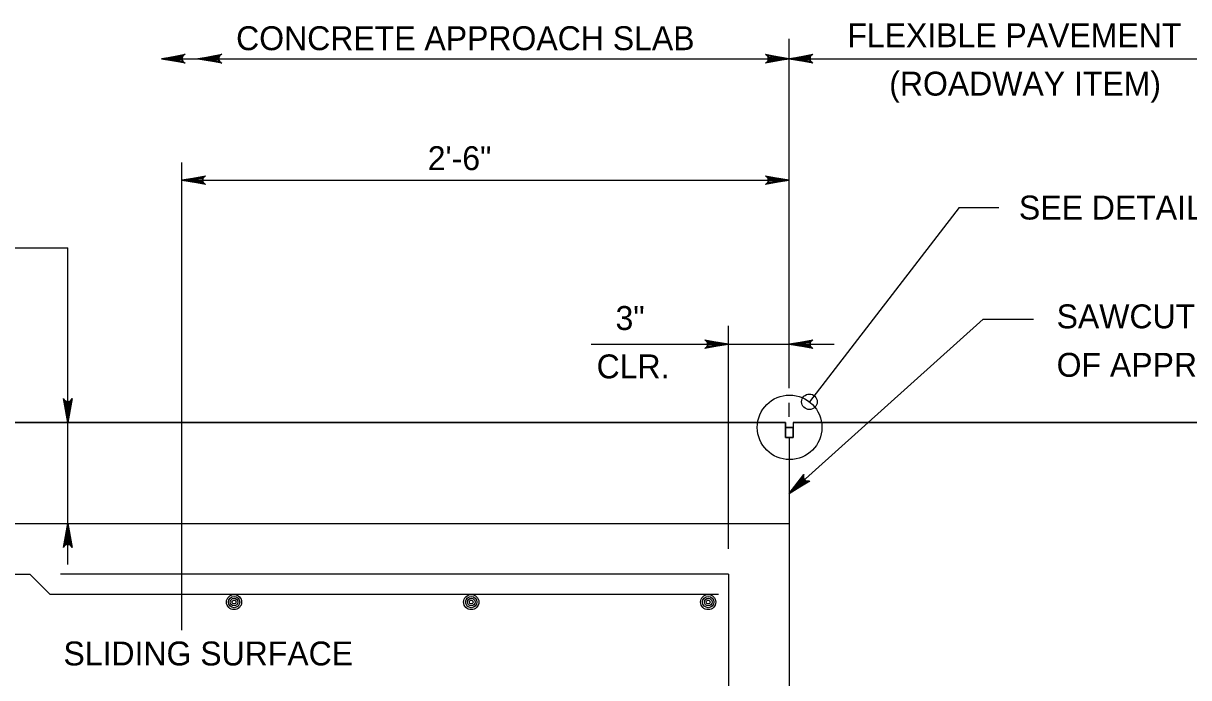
# Model space of a CAD drawing. Extents: x 636530 to 644067, y 294168 to 299122.
# Drawn here: x 639138.6 to 639284.8, y 297431.6 to 297513.7 of the extents above; entities that cross this region are included whole.
import ezdxf

# ---------------------------------------------------------------- set-up
doc = ezdxf.new("R2010")
doc.units = 0
doc.layers.add('1', color=7, linetype='Continuous')

msp = doc.modelspace()

# ---------------------------------------------------------------- linework, layer by layer
at = {"layer": '1'}
for p, q in [((639234.69, 297467.9), (639234.69, 297511.72)), ((639155.94, 297509.24), (639234.69, 297509.24)), ((639234.69, 297509.24), (639301.8, 297509.24)), ((639158.49, 297437.55), (639158.49, 297496.22)), ((639158.49, 297494), (639234.69, 297494)), ((639256.02, 297490.57), (639237.22, 297466.19)), ((639256.02, 297490.57), (639260.99, 297490.57)), ((639092.77, 297485.51), (639144.18, 297485.51)), ((639144.18, 297445.78), (639144.18, 297485.51)), ((639234.69, 297454.67), (639259.02, 297476.54)), ((639259.02, 297476.54), (639265.35, 297476.54)), ((639227.07, 297447.76), (639227.07, 297475.71)), ((639209.86, 297473.42), (639240.35, 297473.42)), ((639234.69, 297464.29), (639234.69, 297466.06)), ((639092.35, 297463.6), (639234.21, 297463.6)), ((639234.21, 297463.6), (639234.21, 297461.7)), ((639235.17, 297463.6), (639235.17, 297461.7)), ((639235.17, 297463.6), (639386.18, 297463.6)), ((639234.21, 297462.97), (639235.17, 297462.97)), ((639234.21, 297461.7), (639235.17, 297461.7)), ((639234.69, 297461.7), (639234.69, 297410.26)), ((639092.35, 297450.9), (639234.69, 297450.9)), ((639092.35, 297444.55), (639139.44, 297444.55)), ((639141.98, 297442.01), (639139.44, 297444.55)), ((639227.07, 297444.55), (639143.25, 297444.55)), ((639227.07, 297444.55), (639227.07, 297417.89)), ((639225.8, 297442.01), (639141.98, 297442.01))]:
    msp.add_line(p, q, dxfattribs=at)
for points in [[(639155.94, 297509.24), (639158.92, 297509.8), (639158.8, 297509.72), (639158.69, 297509.64), (639158.63, 297509.54), (639158.57, 297509.44), (639158.55, 297509.34), (639158.54, 297509.24), (639158.55, 297509.14), (639158.57, 297509.04), (639158.63, 297508.94), (639158.69, 297508.84), (639158.8, 297508.76), (639158.92, 297508.68), (639155.94, 297509.24), (639158.8, 297508.76), (639158.69, 297508.84), (639155.94, 297509.24), (639158.63, 297508.94), (639158.57, 297509.04), (639155.94, 297509.24), (639158.55, 297509.14), (639158.54, 297509.24), (639155.94, 297509.24), (639158.55, 297509.34), (639158.57, 297509.44), (639155.94, 297509.24), (639158.63, 297509.54), (639158.69, 297509.64), (639155.94, 297509.24), (639158.8, 297509.72)], [(639160.51, 297509.24), (639163.49, 297509.8), (639163.38, 297509.72), (639163.26, 297509.64), (639163.2, 297509.54), (639163.14, 297509.44), (639163.12, 297509.34), (639163.11, 297509.24), (639163.12, 297509.14), (639163.14, 297509.04), (639163.2, 297508.94), (639163.26, 297508.84), (639163.38, 297508.76), (639163.49, 297508.68), (639160.51, 297509.24), (639163.38, 297508.76), (639163.26, 297508.84), (639160.51, 297509.24), (639163.2, 297508.94), (639163.14, 297509.04), (639160.51, 297509.24), (639163.12, 297509.14), (639163.11, 297509.24), (639160.51, 297509.24), (639163.12, 297509.34), (639163.14, 297509.44), (639160.51, 297509.24), (639163.2, 297509.54), (639163.26, 297509.64), (639160.51, 297509.24), (639163.38, 297509.72)], [(639234.69, 297509.24), (639231.71, 297508.68), (639231.82, 297508.76), (639231.94, 297508.84), (639232, 297508.94), (639232.06, 297509.04), (639232.07, 297509.14), (639232.09, 297509.24), (639232.07, 297509.34), (639232.06, 297509.44), (639232, 297509.54), (639231.94, 297509.64), (639231.82, 297509.72), (639231.71, 297509.8), (639234.69, 297509.24), (639231.82, 297509.72), (639231.94, 297509.64), (639234.69, 297509.24), (639232, 297509.54), (639232.06, 297509.44), (639234.69, 297509.24), (639232.07, 297509.34), (639232.09, 297509.24), (639234.69, 297509.24), (639232.07, 297509.14), (639232.06, 297509.04), (639234.69, 297509.24), (639232, 297508.94), (639231.94, 297508.84), (639234.69, 297509.24), (639231.82, 297508.76)], [(639234.69, 297509.24), (639237.67, 297509.8), (639237.56, 297509.72), (639237.44, 297509.64), (639237.38, 297509.54), (639237.32, 297509.44), (639237.31, 297509.34), (639237.29, 297509.24), (639237.31, 297509.14), (639237.32, 297509.04), (639237.38, 297508.94), (639237.44, 297508.84), (639237.56, 297508.76), (639237.67, 297508.68), (639234.69, 297509.24), (639237.56, 297508.76), (639237.44, 297508.84), (639234.69, 297509.24), (639237.38, 297508.94), (639237.32, 297509.04), (639234.69, 297509.24), (639237.31, 297509.14), (639237.29, 297509.24), (639234.69, 297509.24), (639237.31, 297509.34), (639237.32, 297509.44), (639234.69, 297509.24), (639237.38, 297509.54), (639237.44, 297509.64), (639234.69, 297509.24), (639237.56, 297509.72)], [(639158.49, 297494), (639161.47, 297494.56), (639161.36, 297494.48), (639161.24, 297494.4), (639161.18, 297494.3), (639161.12, 297494.2), (639161.11, 297494.1), (639161.09, 297494), (639161.11, 297493.9), (639161.12, 297493.8), (639161.18, 297493.7), (639161.24, 297493.6), (639161.36, 297493.52), (639161.47, 297493.44), (639158.49, 297494), (639161.36, 297493.52), (639161.24, 297493.6), (639158.49, 297494), (639161.18, 297493.7), (639161.12, 297493.8), (639158.49, 297494), (639161.11, 297493.9), (639161.09, 297494), (639158.49, 297494), (639161.11, 297494.1), (639161.12, 297494.2), (639158.49, 297494), (639161.18, 297494.3), (639161.24, 297494.4), (639158.49, 297494), (639161.36, 297494.48)], [(639234.69, 297494), (639231.71, 297493.44), (639231.82, 297493.52), (639231.94, 297493.6), (639232, 297493.7), (639232.06, 297493.8), (639232.07, 297493.9), (639232.09, 297494), (639232.07, 297494.1), (639232.06, 297494.2), (639232, 297494.3), (639231.94, 297494.4), (639231.82, 297494.48), (639231.71, 297494.56), (639234.69, 297494), (639231.82, 297494.48), (639231.94, 297494.4), (639234.69, 297494), (639232, 297494.3), (639232.06, 297494.2), (639234.69, 297494), (639232.07, 297494.1), (639232.09, 297494), (639234.69, 297494), (639232.07, 297493.9), (639232.06, 297493.8), (639234.69, 297494), (639232, 297493.7), (639231.94, 297493.6), (639234.69, 297494), (639231.82, 297493.52)], [(639227.07, 297473.42), (639224.09, 297472.86), (639224.2, 297472.94), (639224.32, 297473.02), (639224.38, 297473.12), (639224.44, 297473.22), (639224.45, 297473.32), (639224.47, 297473.42), (639224.45, 297473.52), (639224.44, 297473.62), (639224.38, 297473.72), (639224.32, 297473.82), (639224.2, 297473.9), (639224.09, 297473.98), (639227.07, 297473.42), (639224.2, 297473.9), (639224.32, 297473.82), (639227.07, 297473.42), (639224.38, 297473.72), (639224.44, 297473.62), (639227.07, 297473.42), (639224.45, 297473.52), (639224.47, 297473.42), (639227.07, 297473.42), (639224.45, 297473.32), (639224.44, 297473.22), (639227.07, 297473.42), (639224.38, 297473.12), (639224.32, 297473.02), (639227.07, 297473.42), (639224.2, 297472.94)], [(639234.69, 297473.42), (639237.67, 297473.98), (639237.56, 297473.9), (639237.44, 297473.82), (639237.38, 297473.72), (639237.32, 297473.62), (639237.31, 297473.52), (639237.29, 297473.42), (639237.31, 297473.32), (639237.32, 297473.22), (639237.38, 297473.12), (639237.44, 297473.02), (639237.56, 297472.94), (639237.67, 297472.86), (639234.69, 297473.42), (639237.56, 297472.94), (639237.44, 297473.02), (639234.69, 297473.42), (639237.38, 297473.12), (639237.32, 297473.22), (639234.69, 297473.42), (639237.31, 297473.32), (639237.29, 297473.42), (639234.69, 297473.42), (639237.31, 297473.52), (639237.32, 297473.62), (639234.69, 297473.42), (639237.38, 297473.72), (639237.44, 297473.82), (639234.69, 297473.42), (639237.56, 297473.9)], [(639144.18, 297463.6), (639143.63, 297466.59), (639143.7, 297466.47), (639143.78, 297466.36), (639143.88, 297466.3), (639143.98, 297466.24), (639144.08, 297466.22), (639144.18, 297466.2), (639144.28, 297466.22), (639144.38, 297466.24), (639144.48, 297466.3), (639144.58, 297466.36), (639144.66, 297466.47), (639144.74, 297466.59), (639144.18, 297463.6), (639144.66, 297466.47), (639144.58, 297466.36), (639144.18, 297463.6), (639144.48, 297466.3), (639144.38, 297466.24), (639144.18, 297463.6), (639144.28, 297466.22), (639144.18, 297466.2), (639144.18, 297463.6), (639144.08, 297466.22), (639143.98, 297466.24), (639144.18, 297463.6), (639143.88, 297466.3), (639143.78, 297466.36), (639144.18, 297463.6), (639143.7, 297466.47)], [(639234.69, 297454.67), (639236.53, 297457.08), (639236.5, 297456.95), (639236.47, 297456.81), (639236.49, 297456.7), (639236.52, 297456.58), (639236.57, 297456.5), (639236.62, 297456.41), (639236.7, 297456.35), (639236.78, 297456.28), (639236.89, 297456.25), (639237, 297456.22), (639237.14, 297456.23), (639237.28, 297456.25), (639234.69, 297454.67), (639237.14, 297456.23), (639237, 297456.22), (639234.69, 297454.67), (639236.89, 297456.25), (639236.78, 297456.28), (639234.69, 297454.67), (639236.7, 297456.35), (639236.62, 297456.41), (639234.69, 297454.67), (639236.57, 297456.5), (639236.52, 297456.58), (639234.69, 297454.67), (639236.49, 297456.7), (639236.47, 297456.81), (639234.69, 297454.67), (639236.5, 297456.95)], [(639144.18, 297450.9), (639144.74, 297447.92), (639144.66, 297448.04), (639144.58, 297448.15), (639144.48, 297448.21), (639144.38, 297448.27), (639144.28, 297448.29), (639144.18, 297448.3), (639144.08, 297448.29), (639143.98, 297448.27), (639143.88, 297448.21), (639143.78, 297448.15), (639143.7, 297448.04), (639143.63, 297447.92), (639144.18, 297450.9), (639143.7, 297448.04), (639143.78, 297448.15), (639144.18, 297450.9), (639143.88, 297448.21), (639143.98, 297448.27), (639144.18, 297450.9), (639144.08, 297448.29), (639144.18, 297448.3), (639144.18, 297450.9), (639144.28, 297448.29), (639144.38, 297448.27), (639144.18, 297450.9), (639144.48, 297448.21), (639144.58, 297448.15), (639144.18, 297450.9), (639144.66, 297448.04)]]:
    msp.add_lwpolyline(points, dxfattribs=at)
for points in [[(639092.35, 297450.9), (639234.69, 297450.9), (639234.69, 297410.26), (639310.89, 297410.26), (639331.21, 297430.58), (639386.18, 297430.58), (639386.18, 297433.39), (639391.14, 297435.76), (639381, 297434.37), (639386.18, 297436.91), (639386.18, 297450.9), (639386.18, 297463.6), (639235.17, 297463.6), (639235.17, 297461.7), (639234.21, 297461.7), (639234.21, 297463.6), (639092.35, 297463.6)], [(639234.21, 297461.7), (639235.17, 297461.7), (639235.17, 297462.97), (639234.21, 297462.97)]]:
    msp.add_lwpolyline(points, close=True, dxfattribs=at)
for centre, radius in [((639234.74, 297462.98), 4.05), ((639237.22, 297466.19), 0.977), ((639165.04, 297441.06), 0.952), ((639165.04, 297441.06), 0.714), ((639165.04, 297441.06), 0.476), ((639194.8, 297441.06), 0.952), ((639194.8, 297441.06), 0.714), ((639194.8, 297441.06), 0.476), ((639224.53, 297441.06), 0.952), ((639224.53, 297441.06), 0.714), ((639224.53, 297441.06), 0.476), ((639165.04, 297441.06), 0.238), ((639194.8, 297441.06), 0.238), ((639224.53, 297441.06), 0.238)]:
    msp.add_circle(centre, radius, dxfattribs=at)

# ---------------------------------------------------------------- texts
for s, p in [('CONCRETE APPROACH SLAB', (639165.3, 297510.31)), ('FLEXIBLE PAVEMENT', (639241.98, 297510.68)), ('(ROADWAY ITEM)', (639247.24, 297504.61)), ('2\'-6"', (639189.34, 297495.26)), ('SEE DETAIL G', (639263.51, 297489.06)), ('SAWCUT AND SEAL TO WIDTH', (639268.24, 297475.41)), ('OF APPROACH SLAB', (639268.24, 297469.33)), ('SLIDING SURFACE', (639143.64, 297433.11))]:
    msp.add_text(s, height=3, dxfattribs=at).set_placement(p)
for s, p in [('3"', (639212.9, 297475.2)), ('CLR.', (639210.53, 297469.13))]:
    msp.add_text(s, height=3, rotation=360, dxfattribs=at).set_placement(p)

doc.saveas('drawing.dxf')
